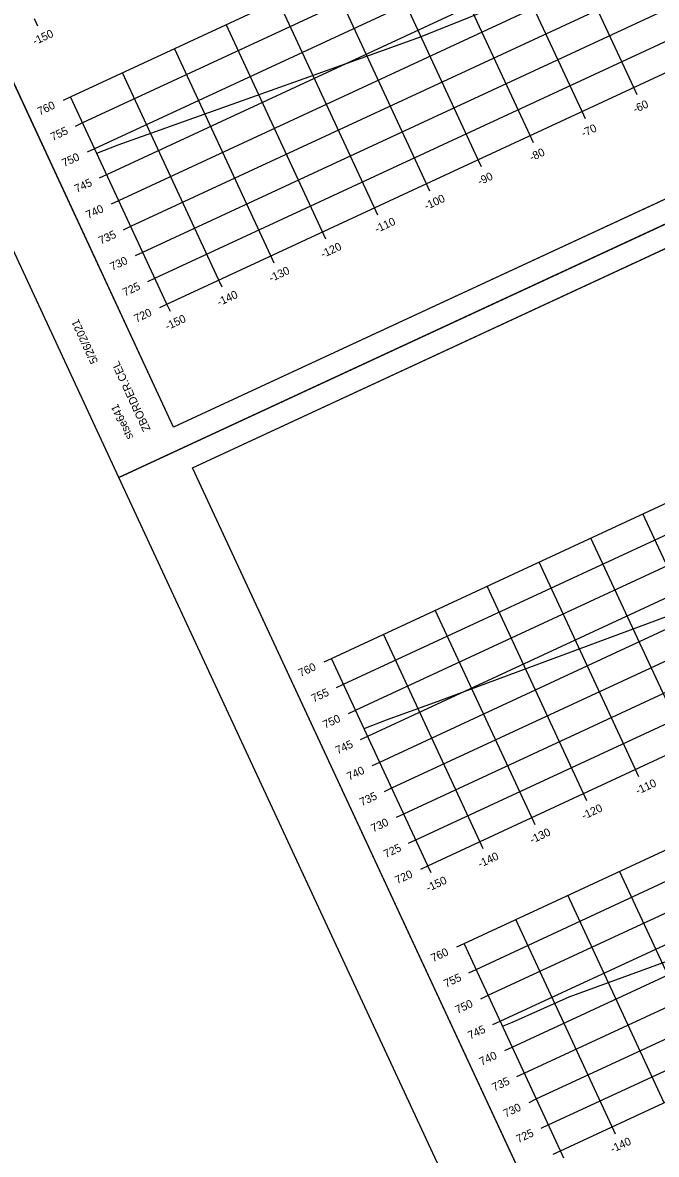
# Model space of a CAD drawing. Extents: x 1354696 to 1366163, y 660729 to 670380.
# Drawn here: x 1358666.2 to 1358777, y 665980.8 to 666178.8 of the extents above; entities that cross this region are included whole.
import ezdxf

# ---------------------------------------------------------------- set-up
doc = ezdxf.new("R2010")
doc.units = 0
for name, color, linetype in [('R_Axis', 7, 'Continuous'), ('R_Axis Annot', 7, 'Continuous'), ('R_Border', 7, 'Continuous'), ('R_Exist Surface', 7, 'Continuous'), ('R_Grid', 7, 'Continuous'), ('R_No Plot', 7, 'Continuous')]:
    doc.layers.add(name, color=color, linetype=linetype)

msp = doc.modelspace()

# ---------------------------------------------------------------- linework, layer by layer
at = {"layer": 'R_Axis'}
for p, q in [((1358691.39, 666129.54), (1358963.5, 666255.87)), ((1358668.82, 666178.16), (1358668.23, 666179.43)), ((1358773.62, 666166.17), (1358773.03, 666167.44)), ((1358673.28, 666165.23), (1358674.55, 666165.82)), ((1358691.39, 666129.54), (1358674.55, 666165.82)), ((1358764.55, 666161.96), (1358763.96, 666163.23)), ((1358675.39, 666160.7), (1358676.66, 666161.29)), ((1358755.48, 666157.75), (1358754.89, 666159.02)), ((1358677.49, 666156.16), (1358678.76, 666156.75)), ((1358737.02, 666031.28), (1359009.12, 666157.61)), ((1358746.4, 666153.54), (1358745.82, 666154.81)), ((1358679.6, 666151.63), (1358680.87, 666152.22)), ((1358737.33, 666149.33), (1358736.75, 666150.6)), ((1358681.7, 666147.09), (1358682.97, 666147.68)), ((1358728.26, 666145.12), (1358727.68, 666146.39)), ((1358683.81, 666142.56), (1358685.08, 666143.15)), ((1358719.19, 666140.91), (1358718.6, 666142.18)), ((1358685.91, 666138.02), (1358687.18, 666138.61)), ((1358710.12, 666136.69), (1358709.53, 666137.96)), ((1358688.02, 666133.49), (1358689.29, 666134.08)), ((1358701.05, 666132.48), (1358700.46, 666133.75)), ((1358690.12, 666128.95), (1358691.39, 666129.54)), ((1358691.98, 666128.27), (1358691.39, 666129.54)), ((1358760.18, 665981.39), (1359032.28, 666107.72)), ((1358718.9, 666066.97), (1358720.17, 666067.56)), ((1358737.02, 666031.28), (1358720.17, 666067.56)), ((1358721.01, 666062.43), (1358722.28, 666063.02)), ((1358723.11, 666057.9), (1358724.38, 666058.49)), ((1358725.22, 666053.36), (1358726.49, 666053.95)), ((1358727.32, 666048.83), (1358728.59, 666049.42)), ((1358773.89, 666046.85), (1358773.3, 666048.12)), ((1358729.43, 666044.29), (1358730.7, 666044.88)), ((1358764.82, 666042.64), (1358764.23, 666043.91)), ((1358731.54, 666039.76), (1358732.8, 666040.35)), ((1358755.75, 666038.43), (1358755.16, 666039.7)), ((1358733.64, 666035.22), (1358734.91, 666035.81)), ((1358746.68, 666034.22), (1358746.09, 666035.49)), ((1358735.75, 666030.69), (1358737.02, 666031.28)), ((1358737.61, 666030.01), (1358737.02, 666031.28)), ((1358742.06, 666017.08), (1358743.33, 666017.67)), ((1358760.18, 665981.39), (1358743.33, 666017.67)), ((1358744.17, 666012.55), (1358745.44, 666013.14)), ((1358746.27, 666008.01), (1358747.54, 666008.6)), ((1358748.38, 666003.48), (1358749.65, 666004.07)), ((1358750.48, 665998.94), (1358751.75, 665999.53)), ((1358752.59, 665994.41), (1358753.86, 665995)), ((1358754.7, 665989.87), (1358755.97, 665990.46)), ((1358756.8, 665985.34), (1358758.07, 665985.93)), ((1358769.84, 665984.33), (1358769.25, 665985.6)), ((1358758.91, 665980.8), (1358760.18, 665981.39)), ((1358760.77, 665980.12), (1358760.18, 665981.39))]:
    msp.add_line(p, q, dxfattribs=at)
at = {"layer": 'R_Border'}
for p, q in [((1358692.56, 666108.03), (1358606.04, 666294.39)), ((1358979.34, 666241.18), (1358692.56, 666108.03)), ((1358695.88, 666100.89), (1358982.66, 666234.03)), ((1358692.56, 666108.03), (1358692.56, 666108.03)), ((1358782.4, 665914.53), (1358695.88, 666100.89))]:
    msp.add_line(p, q, dxfattribs=at)
at = {"layer": 'R_Exist Surface'}
for points in [[(1358679.14, 666155.95), (1358682.85, 666157.41), (1358726.96, 666173.13), (1358735.71, 666176.28), (1358771.72, 666190.8)], [(1358725.87, 666055.28), (1358729.76, 666056.78), (1358738.8, 666060.04), (1358782.36, 666076.2)], [(1358750.04, 666003.23), (1358751.8, 666003.92), (1358761.71, 666008.36), (1358804.35, 666023.91)]]:
    msp.add_lwpolyline(points, dxfattribs=at)
at = {"layer": 'R_Grid'}
for p, q in [((1358674.55, 666165.82), (1358946.65, 666292.15)), ((1358676.66, 666161.29), (1358948.76, 666287.62)), ((1358678.76, 666156.75), (1358950.87, 666283.08)), ((1358680.87, 666152.22), (1358952.97, 666278.55)), ((1358682.97, 666147.68), (1358955.08, 666274.01)), ((1358685.08, 666143.15), (1358957.18, 666269.48)), ((1358687.18, 666138.61), (1358959.29, 666264.94)), ((1358689.29, 666134.08), (1358961.39, 666260.41)), ((1358691.39, 666129.54), (1358963.5, 666255.87)), ((1358773.03, 666167.44), (1358756.18, 666203.72)), ((1358763.96, 666163.23), (1358747.11, 666199.51)), ((1358754.89, 666159.02), (1358738.04, 666195.3)), ((1358720.17, 666067.56), (1358992.28, 666193.89)), ((1358745.82, 666154.81), (1358728.97, 666191.09)), ((1358722.28, 666063.02), (1358994.38, 666189.35)), ((1358736.75, 666150.6), (1358719.9, 666186.88)), ((1358724.38, 666058.49), (1358996.49, 666184.82)), ((1358727.68, 666146.39), (1358710.83, 666182.67)), ((1358726.49, 666053.95), (1358998.59, 666180.28)), ((1358718.6, 666142.18), (1358701.76, 666178.46)), ((1358709.53, 666137.96), (1358692.69, 666174.25)), ((1358728.59, 666049.42), (1359000.7, 666175.75)), ((1358730.7, 666044.88), (1359002.8, 666171.21)), ((1358700.46, 666133.75), (1358683.62, 666170.03)), ((1358732.8, 666040.35), (1359004.91, 666166.68)), ((1358691.39, 666129.54), (1358674.55, 666165.82)), ((1358734.91, 666035.81), (1359007.01, 666162.14)), ((1358737.02, 666031.28), (1359009.12, 666157.61)), ((1358743.33, 666017.67), (1359015.44, 666144)), ((1358745.44, 666013.14), (1359017.54, 666139.47)), ((1358747.54, 666008.6), (1359019.65, 666134.93)), ((1358749.65, 666004.07), (1359021.75, 666130.4)), ((1358751.75, 665999.53), (1359023.86, 666125.86)), ((1358753.86, 665995), (1359025.96, 666121.33)), ((1358755.97, 665990.46), (1359028.07, 666116.79)), ((1358758.07, 665985.93), (1359030.17, 666112.26)), ((1358760.18, 665981.39), (1359032.28, 666107.72)), ((1358791.44, 666056.54), (1358774.59, 666092.83)), ((1358782.37, 666052.33), (1358765.52, 666088.61)), ((1358773.3, 666048.12), (1358756.45, 666084.4)), ((1358764.23, 666043.91), (1358747.38, 666080.19)), ((1358755.16, 666039.7), (1358738.31, 666075.98)), ((1358746.09, 666035.49), (1358729.24, 666071.77)), ((1358737.02, 666031.28), (1358720.17, 666067.56)), ((1358787.39, 665994.03), (1358770.54, 666030.31)), ((1358778.32, 665989.81), (1358761.47, 666026.1)), ((1358769.25, 665985.6), (1358752.4, 666021.88)), ((1358760.18, 665981.39), (1358743.33, 666017.67))]:
    msp.add_line(p, q, dxfattribs=at)
at = {"layer": 'R_No Plot'}
msp.add_line((1358682.99, 666099.2), (1358985.33, 666239.57), dxfattribs=at)
msp.add_line((1358682.99, 666099.2), (1358985.33, 666239.57), dxfattribs=at)
for points in [[(1358593.15, 666292.7), (1358895.49, 666433.07), (1358985.33, 666239.57), (1358682.98, 666099.2)], [(1358818.21, 666392.89), (1358836.01, 666401.15), (1358840.17, 666392.19), (1358854.78, 666398.98), (1358875.82, 666408.75), (1358887.79, 666383.26), (1358908.84, 666393.03), (1358979.34, 666241.18), (1358692.56, 666108.03), (1358606.04, 666294.39)], [(1358682.98, 666099.2), (1358985.33, 666239.57), (1359075.16, 666046.07), (1358772.82, 665905.7)], [(1358908.05, 666199.39), (1358925.84, 666207.65), (1358930, 666198.69), (1358944.62, 666205.48), (1358965.66, 666215.25), (1358977.62, 666189.76), (1358998.67, 666199.53), (1359069.18, 666047.68), (1358782.4, 665914.53), (1358695.88, 666100.89)]]:
    msp.add_lwpolyline(points, close=True, dxfattribs=at)

# ---------------------------------------------------------------- texts
at = {"layer": 'R_Axis Annot'}
for s, p in [('-150', (1358668.29, 666174.82)), ('760', (1358669.14, 666162.54)), ('-60', (1358773.26, 666162.92)), ('755', (1358671.41, 666158.08)), ('-70', (1358764.22, 666158.72)), ('-80', (1358755.15, 666154.51)), ('750', (1358673.41, 666153.5)), ('-90', (1358746.08, 666150.3)), ('745', (1358675.62, 666149.01)), ('-100', (1358736.75, 666145.97)), ('740', (1358677.62, 666144.43)), ('-110', (1358728.09, 666141.95)), ('735', (1358679.83, 666139.94)), ('-120', (1358718.66, 666137.57)), ('730', (1358681.83, 666135.36)), ('-130', (1358709.59, 666133.36)), ('725', (1358684.04, 666130.87)), ('-140', (1358700.52, 666129.15)), ('720', (1358686.04, 666126.28)), ('-150', (1358691.45, 666124.94)), ('760', (1358714.76, 666064.27)), ('755', (1358717.03, 666059.82)), ('750', (1358719.03, 666055.23)), ('745', (1358721.24, 666050.75)), ('740', (1358723.24, 666046.16)), ('-110', (1358773.71, 666043.68)), ('735', (1358725.45, 666041.68)), ('-120', (1358764.28, 666039.31)), ('730', (1358727.45, 666037.09)), ('-130', (1358755.21, 666035.1)), ('725', (1358729.67, 666032.61)), ('-140', (1358746.14, 666030.88)), ('720', (1358731.66, 666028.02)), ('-150', (1358737.07, 666026.67)), ('760', (1358737.92, 666014.39)), ('755', (1358740.19, 666009.93)), ('750', (1358742.19, 666005.35)), ('745', (1358744.4, 666000.86)), ('740', (1358746.4, 665996.28)), ('735', (1358748.62, 665991.79)), ('730', (1358750.61, 665987.21)), ('725', (1358752.83, 665982.72)), ('-140', (1358769.3, 665981))]:
    msp.add_text(s, height=1.4, rotation=24.9042, dxfattribs=at).set_placement(p)
at = {"layer": 'R_Border'}
for s, p in [('5/26/2021', (1358679.38, 666119.48)), ('ZBORDER.CEL', (1358688.55, 666107.63)), ('stse641', (1358685.53, 666106.23))]:
    msp.add_text(s, height=1.4, rotation=114.9042, dxfattribs=at).set_placement(p)

doc.saveas('drawing.dxf')
